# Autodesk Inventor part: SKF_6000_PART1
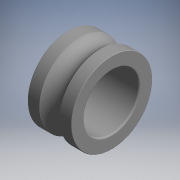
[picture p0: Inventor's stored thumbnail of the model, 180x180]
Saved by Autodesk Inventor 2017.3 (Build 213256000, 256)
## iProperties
Part Number: SKF_6000_PART1
Material: Generic
Catalog Web Link: www.cadenas.de
Description: -Deep groove ball bearings
Vendor: SKF
Document SubType Name: Modeling
Designer: partserver
Manufacturer: SKF
Mass: 19 g
Surface Area: 8.07797 cm^2
Volume: 0.646194 cm^3
Density: 1 g/cm^3
Appearance: PSOLRGB-175-175-175
Category: PARTsolutions
Company: SKF
Title: SKF_6000_PART1
Author: Cadenas PARTsolutions
Comments: Deep groove ball bearings
PSOL_IDENT_0: {$CADENAS_DATA\23d-libs\skf\bearings_units_and_housings\ball_bearings\deep_groove_ball_bearings\bb1_
PSOL_IDENT_1: 001_101.prj},194 {VTYP=3D},{NB=SKF_6000_PART1},{LINA=SKF_6000_PART1},{NN=BB1_001_101_PART1},{NOPRJ=T
PSOL_IDENT_2: RUE},{DATE=18.06.2021 07:30:58},{GEOMDATE=16.06.2021 12:48:44},{VERSION=},{LINEID=5840},{WBVAR=},{WB
PSOL_IDENT_3: NUMERIC=}  {NB=SKF_6000_PART1},{LINA=SKF_6000_PART1},{KT=DUMMY},{DESIGNATION=6000},{R12=0.30},{DD=10
PSOL_IDENT_4: .000},{D=26.000},{B=8.000},{C=},{CX=},{CXX=},{CA=0.000},{XXVARIANT=},{XXDESIGN=Single row},{XXSEALIN
PSOL_IDENT_5: G=No seals},{DESIGN=dgbb1},{DESIGNIR=dgbb1},{VARIANT=},{DD1=14.80},{DD2=},{DD2X=},{DD2A=0.00},{D1=21
PSOL_IDENT_6: .20},{D1X=MIN},{D2=22.6},{D2A=22.60},{D3=},{D3X=},{D3A=0.000},{D4=},{HH=MIN},{BB=MIN},{BBX=},{BBA=0.
PSOL_IDENT_7: 000},{FF=},{R0MAX=MIN},{R0=MIN},{PITCH=17.80},{DW=4.762},{DDAMIN=12.000},{DDAMAX=MIN},{DDBMIN=MIN},{
PSOL_IDENT_8: DDBMAX=MIN},{DBMIN=MIN},{DAMAX=24.000},{BBAMIN=MIN},{CAMAX=MIN},{RAMAX=0.300},{LOAD1=4.750},{LOAD2=1
PSOL_IDENT_9: .960},{LOAD3=0.083},{SPEED1=67000},{SPEED2=40000},{KR=0.025},{F0=12.000},{Z=7},{II=1},{MASS=0.019},{
PSOL_IDENT_10: BEARING=6000},{RING=},{HELP=2.400},{HELP2=1.700},{DD1ALG=7.400},{YALG=7.400},{PITCH1=17.800},{DW1=4.
PSOL_IDENT_11: 762},{YALG1=10.600},{HALG1=2.400},{SH=7.400},{CU=0.648},{HALG=2.4},{B1=0},{SHIELDHELP=1},{D4A=0.000}
PSOL_IDENT_12: ,{FFA=0.000},{RS1=}
NB: SKF_6000_PART1
NT: Deep groove ball bearings
NBSYN: SKF_$DESIGNATION._PART1
LINA: SKF_6000_PART1
CATALOG: SKF
DESIGNATION: 6000
R12: 0.3
DD: 10
D: 26
B: 8
D2: 22.6
LOAD1: 4.75
LOAD2: 1.96
LOAD3: 0.083
SPEED1: 67000
SPEED2: 40000
BEARING: 6000
SUPPLIER: SKF
ARTICLENO: SKF_6000_PART1
BOMINFO: SKF_6000_PART1
CREATOR: CADENAS GmbH
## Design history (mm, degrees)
sketch "Sketch_54"
  geometry: L1 (100, 0)-(-100, 0); L2 (0.3, 5)-(7.7, 5); L3 (8, 5.3)-(8, 7.3); L4 (7.9, 7.4)-(5.849, 7.4); L5 (2.151, 7.4)-(0.1, 7.4); L6 (0, 7.3)-(0, 5.3); A1 r 0.3 centre (0.3, 5.3) between (0, 5.3) and (0.3, 5); A2 r 0.3 centre (7.7, 5.3) between (7.7, 5) and (8, 5.3); A3 r 0.1 centre (7.9, 7.3) between (8, 7.3) and (7.9, 7.4); A4 r 2.381 centre (4, 8.9) between (2.151, 7.4) and (5.849, 7.4); A5 r 0.1 centre (0.1, 7.3) between (0.1, 7.4) and (0, 7.3)
  constraints: 12 end point, 10 point on circle, 5 centre point
revolve "Revolution1" sketch "Sketch_54" stored, may be unused: angle "d0" = 360 deg
body "Solid1"
